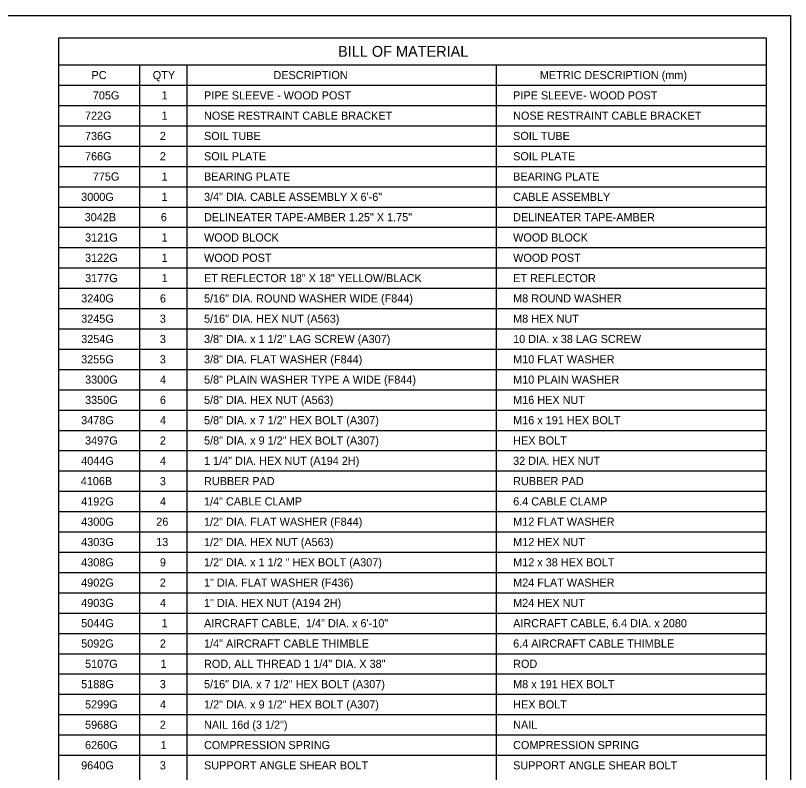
# Model space of a CAD drawing. Extents: x 49991.4 to 50021, y 49987.6 to 50011.4.
# Drawn here: x 50011.02 to 50016.75, y 49993.41 to 49999 of the extents above; entities that cross this region are included whole.
import ezdxf

# ---------------------------------------------------------------- set-up
doc = ezdxf.new("R2010")
doc.units = 0
doc.layers.add('Level 1', color=7, linetype='Continuous')
doc.layers.add('Level 2', color=7, linetype='Continuous')

msp = doc.modelspace()

# ---------------------------------------------------------------- linework, layer by layer
at = {"layer": 'Level 1'}
msp.add_lwpolyline([(49999.3835, 49998.9992), (50016.7501, 49998.9992), (50016.7501, 49987.7988), (49999.3835, 49987.7988)], close=True, dxfattribs=at)
at = {"layer": 'Level 2'}
for p, q in [((50011.3397, 49998.8342), (50011.3397, 49991.4286)), ((50011.3397, 49998.8342), (50016.5707, 49998.8342)), ((50016.5707, 49998.8342), (50016.5707, 49991.4286)), ((50011.3397, 49998.6342), (50016.5707, 49998.6342)), ((50011.9397, 49998.6342), (50011.9397, 49991.4286)), ((50012.2897, 49998.6342), (50012.2897, 49991.4286)), ((50014.574, 49998.6342), (50014.574, 49991.4286)), ((50011.3397, 49998.4842), (50016.5707, 49998.4842)), ((50011.3397, 49998.3342), (50016.5707, 49998.3342)), ((50011.3397, 49998.1842), (50016.5707, 49998.1842)), ((50011.3397, 49998.0342), (50016.5707, 49998.0342)), ((50011.3397, 49997.8842), (50016.5707, 49997.8842)), ((50011.3397, 49997.7342), (50016.5707, 49997.7342)), ((50011.3397, 49997.5842), (50016.5707, 49997.5842)), ((50011.3397, 49997.4342), (50016.5707, 49997.4342)), ((50011.3397, 49997.2842), (50016.5707, 49997.2842)), ((50011.3397, 49997.1342), (50016.5707, 49997.1342)), ((50011.3397, 49996.9842), (50016.5707, 49996.9842)), ((50011.3397, 49996.8342), (50016.5707, 49996.8342)), ((50011.3397, 49996.6842), (50016.5707, 49996.6842)), ((50011.3397, 49996.5342), (50016.5707, 49996.5342)), ((50011.3397, 49996.3842), (50016.5707, 49996.3842)), ((50011.3397, 49996.2342), (50016.5707, 49996.2342)), ((50011.3397, 49996.0842), (50016.5707, 49996.0842)), ((50011.3397, 49995.9342), (50016.5707, 49995.9342)), ((50011.3397, 49995.7842), (50016.5707, 49995.7842)), ((50011.3397, 49995.6342), (50016.5707, 49995.6342)), ((50011.3397, 49995.4842), (50016.5707, 49995.4842)), ((50011.3397, 49995.3342), (50016.5707, 49995.3342)), ((50011.3397, 49995.1842), (50016.5707, 49995.1842)), ((50011.3397, 49995.0342), (50016.5707, 49995.0342)), ((50011.3397, 49994.8842), (50016.5707, 49994.8842)), ((50011.3397, 49994.7342), (50016.5707, 49994.7342)), ((50011.3397, 49994.5842), (50016.5707, 49994.5842)), ((50011.3397, 49994.4342), (50016.5707, 49994.4342)), ((50011.3397, 49994.2842), (50016.5707, 49994.2842)), ((50011.3397, 49994.1342), (50016.5707, 49994.1342)), ((50011.3397, 49993.9842), (50016.5707, 49993.9842)), ((50011.3397, 49993.8342), (50016.5707, 49993.8342)), ((50011.3397, 49993.6842), (50016.5707, 49993.6842)), ((50011.3397, 49993.5342), (50016.5707, 49993.5342))]:
    msp.add_line(p, q, dxfattribs=at)

# ---------------------------------------------------------------- texts
for s, height, p in [('BILL OF MATERIAL', 0.08, (50013.4065, 49998.6942)), ('PC', 0.06, (50011.5848, 49998.5292)), ('QTY', 0.06, (50012.0373, 49998.5292)), ('DESCRIPTION', 0.06, (50012.9293, 49998.5292)), ('METRIC DESCRIPTION (mm)', 0.06, (50014.898, 49998.5292)), ('705G', 0.06, (50011.5941, 49998.3792)), ('1', 0.06, (50012.1018, 49998.3792)), ('PIPE SLEEVE - WOOD POST', 0.06, (50012.4161, 49998.3792)), ('PIPE SLEEVE- WOOD POST', 0.06, (50014.7004, 49998.3792)), ('  722G', 0.06, (50011.492, 49998.2292)), ('1', 0.06, (50012.1018, 49998.2292)), ('NOSE RESTRAINT CABLE BRACKET', 0.06, (50012.4161, 49998.2292)), ('NOSE RESTRAINT CABLE BRACKET', 0.06, (50014.7004, 49998.2292)), ('  736G', 0.06, (50011.492, 49998.0792)), ('2', 0.06, (50012.0895, 49998.0792)), ('SOIL TUBE', 0.06, (50012.4161, 49998.0792)), ('SOIL TUBE', 0.06, (50014.7004, 49998.0792)), ('  766G', 0.06, (50011.492, 49997.9292)), ('2', 0.06, (50012.0895, 49997.9292)), ('SOIL PLATE', 0.06, (50012.4161, 49997.9292)), ('SOIL PLATE', 0.06, (50014.7004, 49997.9292)), ('775G', 0.06, (50011.5941, 49997.7792)), ('1', 0.06, (50012.1018, 49997.7792)), ('BEARING PLATE', 0.06, (50012.4161, 49997.7792)), ('BEARING PLATE', 0.06, (50014.7004, 49997.7792)), (' 3000G', 0.06, (50011.4861, 49997.6292)), ('1', 0.06, (50012.1018, 49997.6292)), ('3/4" DIA. CABLE ASSEMBLY X 6\'-6" ', 0.06, (50012.4161, 49997.6292)), ('CABLE ASSEMBLY', 0.06, (50014.7004, 49997.6292)), ('3042B', 0.06, (50011.5342, 49997.4792)), ('6', 0.06, (50012.097, 49997.4792)), ('DELINEATER TAPE-AMBER 1.25" X 1.75"', 0.06, (50012.4161, 49997.4792)), ('DELINEATER TAPE-AMBER ', 0.06, (50014.7004, 49997.4792)), ('3121G', 0.06, (50011.5371, 49997.3292)), ('1', 0.06, (50012.1018, 49997.3292)), ('WOOD BLOCK', 0.06, (50012.4161, 49997.3292)), ('WOOD BLOCK', 0.06, (50014.7004, 49997.3292)), ('3122G', 0.06, (50011.5371, 49997.1792)), ('1', 0.06, (50012.1018, 49997.1792)), ('WOOD POST', 0.06, (50012.4161, 49997.1792)), ('WOOD POST', 0.06, (50014.7004, 49997.1792)), ('3177G', 0.06, (50011.5371, 49997.0292)), ('1', 0.06, (50012.1018, 49997.0292)), ('ET REFLECTOR 18" X 18" YELLOW/BLACK', 0.06, (50012.4161, 49997.0292)), ('ET REFLECTOR', 0.06, (50014.7004, 49997.0292)), (' 3240G', 0.06, (50011.4861, 49996.8792)), ('6', 0.06, (50012.0902, 49996.8792)), ('5/16" DIA. ROUND WASHER WIDE (F844)', 0.06, (50012.4161, 49996.8792)), ('M8 ROUND WASHER', 0.06, (50014.7004, 49996.8792)), (' 3245G', 0.06, (50011.4861, 49996.7292)), ('3', 0.06, (50012.0895, 49996.7292)), ('5/16" DIA. HEX NUT (A563)', 0.06, (50012.4161, 49996.7292)), ('M8 HEX NUT', 0.06, (50014.7004, 49996.7292)), (' 3254G', 0.06, (50011.4861, 49996.5792)), ('3', 0.06, (50012.0895, 49996.5792)), ('3/8" DIA. x 1 1/2" LAG SCREW (A307)', 0.06, (50012.4161, 49996.5792)), ('10 DIA. x 38 LAG SCREW', 0.06, (50014.7004, 49996.5792)), (' 3255G', 0.06, (50011.4861, 49996.4292)), ('3', 0.06, (50012.0895, 49996.4292)), ('3/8" DIA. FLAT WASHER (F844)', 0.06, (50012.4161, 49996.4292)), ('M10 FLAT WASHER', 0.06, (50014.7004, 49996.4292)), ('3300G', 0.06, (50011.5371, 49996.2792)), ('4', 0.06, (50012.0907, 49996.2792)), ('5/8" PLAIN WASHER TYPE A WIDE (F844)', 0.06, (50012.4161, 49996.2792)), ('M10 PLAIN WASHER', 0.06, (50014.7004, 49996.2792)), ('3350G', 0.06, (50011.5371, 49996.1292)), ('6', 0.06, (50012.0902, 49996.1292)), ('5/8" DIA. HEX NUT (A563)', 0.06, (50012.4161, 49996.1292)), ('M16 HEX NUT', 0.06, (50014.7004, 49996.1292)), (' 3478G', 0.06, (50011.4861, 49995.9792)), ('4', 0.06, (50012.0907, 49995.9792)), ('5/8" DIA. x 7 1/2" HEX BOLT (A307)', 0.06, (50012.4161, 49995.9792)), ('M16 x 191 HEX BOLT', 0.06, (50014.7004, 49995.9792)), ('3497G', 0.06, (50011.5371, 49995.8292)), ('2', 0.06, (50012.0895, 49995.8292)), ('5/8" DIA. x 9 1/2" HEX BOLT (A307)', 0.06, (50012.4161, 49995.8292)), ('HEX BOLT', 0.06, (50014.7004, 49995.8292)), (' 4044G', 0.06, (50011.4861, 49995.6792)), ('4', 0.06, (50012.0907, 49995.6792)), ('1 1/4" DIA. HEX NUT (A194 2H)', 0.06, (50012.4161, 49995.6792)), ('32 DIA. HEX NUT', 0.06, (50014.7004, 49995.6792)), (' 4106B', 0.06, (50011.4832, 49995.5292)), ('3', 0.06, (50012.0895, 49995.5292)), ('RUBBER PAD', 0.06, (50012.4161, 49995.5292)), ('RUBBER PAD', 0.06, (50014.7004, 49995.5292)), (' 4192G', 0.06, (50011.4861, 49995.3792)), ('4', 0.06, (50012.0907, 49995.3792)), ('1/4" CABLE CLAMP', 0.06, (50012.4161, 49995.3792)), ('6.4 CABLE CLAMP', 0.06, (50014.7004, 49995.3792)), (' 4300G', 0.06, (50011.4861, 49995.2292)), ('26', 0.06, (50012.0632, 49995.2292)), ('1/2" DIA. FLAT WASHER (F844)', 0.06, (50012.4161, 49995.2292)), ('M12 FLAT WASHER', 0.06, (50014.7004, 49995.2292)), (' 4303G', 0.06, (50011.4861, 49995.0792)), ('13', 0.06, (50012.0626, 49995.0792)), ('1/2" DIA. HEX NUT (A563)', 0.06, (50012.4161, 49995.0792)), ('M12 HEX NUT', 0.06, (50014.7004, 49995.0792)), (' 4308G', 0.06, (50011.4861, 49994.9292)), ('9', 0.06, (50012.0902, 49994.9292)), ('1/2" DIA. x 1 1/2 " HEX BOLT (A307)', 0.06, (50012.4161, 49994.9292)), ('M12 x 38 HEX BOLT', 0.06, (50014.7004, 49994.9292)), (' 4902G', 0.06, (50011.4861, 49994.7792)), ('2', 0.06, (50012.0895, 49994.7792)), ('1" DIA. FLAT WASHER (F436)', 0.06, (50012.4161, 49994.7792)), ('M24 FLAT WASHER', 0.06, (50014.7004, 49994.7792)), (' 4903G', 0.06, (50011.4861, 49994.6292)), ('4', 0.06, (50012.0907, 49994.6292)), ('1" DIA. HEX NUT (A194 2H)', 0.06, (50012.4161, 49994.6292)), ('M24 HEX NUT', 0.06, (50014.7004, 49994.6292)), (' 5044G', 0.06, (50011.4861, 49994.4792)), ('1', 0.06, (50012.1018, 49994.4792)), ('AIRCRAFT CABLE,  1/4" DIA. x 6\'-10"', 0.06, (50012.4161, 49994.4792)), ('AIRCRAFT CABLE, 6.4 DIA. x 2080', 0.06, (50014.7004, 49994.4792)), (' 5092G', 0.06, (50011.4861, 49994.3292)), ('2', 0.06, (50012.0895, 49994.3292)), ('1/4" AIRCRAFT CABLE THIMBLE', 0.06, (50012.4161, 49994.3292)), ('6.4 AIRCRAFT CABLE THIMBLE', 0.06, (50014.7004, 49994.3292)), ('5107G', 0.06, (50011.5371, 49994.1792)), ('1', 0.06, (50012.0949, 49994.1792)), ('ROD, ALL THREAD 1 1/4" DIA. X 38"', 0.06, (50012.4161, 49994.1792)), ('ROD', 0.06, (50014.7004, 49994.1792)), (' 5188G', 0.06, (50011.4861, 49994.0292)), ('3', 0.06, (50012.0895, 49994.0292)), ('5/16" DIA. x 7 1/2" HEX BOLT (A307)', 0.06, (50012.4161, 49994.0292)), ('M8 x 191 HEX BOLT', 0.06, (50014.7004, 49994.0292)), ('5299G', 0.06, (50011.5371, 49993.8792)), ('4', 0.06, (50012.0907, 49993.8792)), ('1/2" DIA. x 9 1/2" HEX BOLT (A307)', 0.06, (50012.4161, 49993.8792)), ('HEX BOLT', 0.06, (50014.7004, 49993.8792)), ('5968G', 0.06, (50011.5371, 49993.7292)), ('2', 0.06, (50012.0895, 49993.7292)), ('NAIL 16d (3 1/2")', 0.06, (50012.4161, 49993.7292)), ('NAIL', 0.06, (50014.7004, 49993.7292)), ('6260G', 0.06, (50011.5371, 49993.5792)), ('1', 0.06, (50012.0949, 49993.5792)), ('COMPRESSION SPRING', 0.06, (50012.4161, 49993.5792)), ('COMPRESSION SPRING', 0.06, (50014.7004, 49993.5792)), (' 9640G', 0.06, (50011.4861, 49993.4292)), ('3', 0.06, (50012.0895, 49993.4292)), ('SUPPORT ANGLE SHEAR BOLT', 0.06, (50012.4161, 49993.4292)), ('SUPPORT ANGLE SHEAR BOLT', 0.06, (50014.7004, 49993.4292))]:
    msp.add_text(s, height=height, dxfattribs=at).set_placement(p)

doc.saveas('drawing.dxf')
